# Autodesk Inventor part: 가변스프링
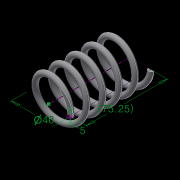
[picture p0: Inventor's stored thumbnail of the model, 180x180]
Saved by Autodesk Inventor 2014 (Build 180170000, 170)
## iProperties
Created: 2018-04
Part Number: 가변스프링
Material: 스테인레스 스틸
Document SubType Name: Modeling
Designer: 703
Density: 8.08 g/cm^3
Appearance: 반연마
Mass: 98.283 g
Surface Area: 98.789 cm^2
Volume: 12.1637 cm^3
Author: 703
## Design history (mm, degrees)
sketch "스케치1"
  geometry: L1 (0, 0)-(20, 0); L2 (20, 0)-(20, 75.25); L3 (20, 75.25)-(0, 75.25); L4 (0, 75.25)-(0, 0); C1 r 2.5 at (20, 0); 1 further point
  constraints: 8 end point, 2 coincident, 2 parallel, 1 centre point, 1 horizontal, 1 perpendicular
  dimensions: "d1" = 40 diameter of L2 L4; "d2" = 75.25 distance of L1.end L2.end (derived); "d3" = 5 diameter of C1
feature "코일1" sketch "스케치1" pitch "d4" = 10; turns "d6" = 5; dims "d5" = 75.25 (= d2), "d7" = 0, angle "d8" = 90 deg, angle "d9" = 90 deg, "d10" = 0, "d11" = 0
sketch "스케치2"
  geometry: L1 (-17.5, 0)-(-22.5, 0) reference; 1 further point
  constraints: 1 horizontal alignment
extrude "돌출1" cut sketch "스케치2" distance "d12" = 10; taper "d13" = 0 deg
node "작업 평면1"
sketch "스케치3"
  geometry: L1 (-22.5, 0)-(-17.5, 0) reference; 1 further point
  constraints: 1 horizontal alignment
extrude "돌출2" cut sketch "스케치3" distance "d14" = 10; taper "d15" = 0 deg
node "솔리드1"
node "절단 모서리 투영1"
node "절단 모서리 투영2"
